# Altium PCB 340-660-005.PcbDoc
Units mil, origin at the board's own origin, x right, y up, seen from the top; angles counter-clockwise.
Board outline 988 x 985 mil, 2 copper layers (Top Layer, Bottom Layer), stack 61.756 mil thick; 90 components, 41 nets, 201 pads, 77 vias.
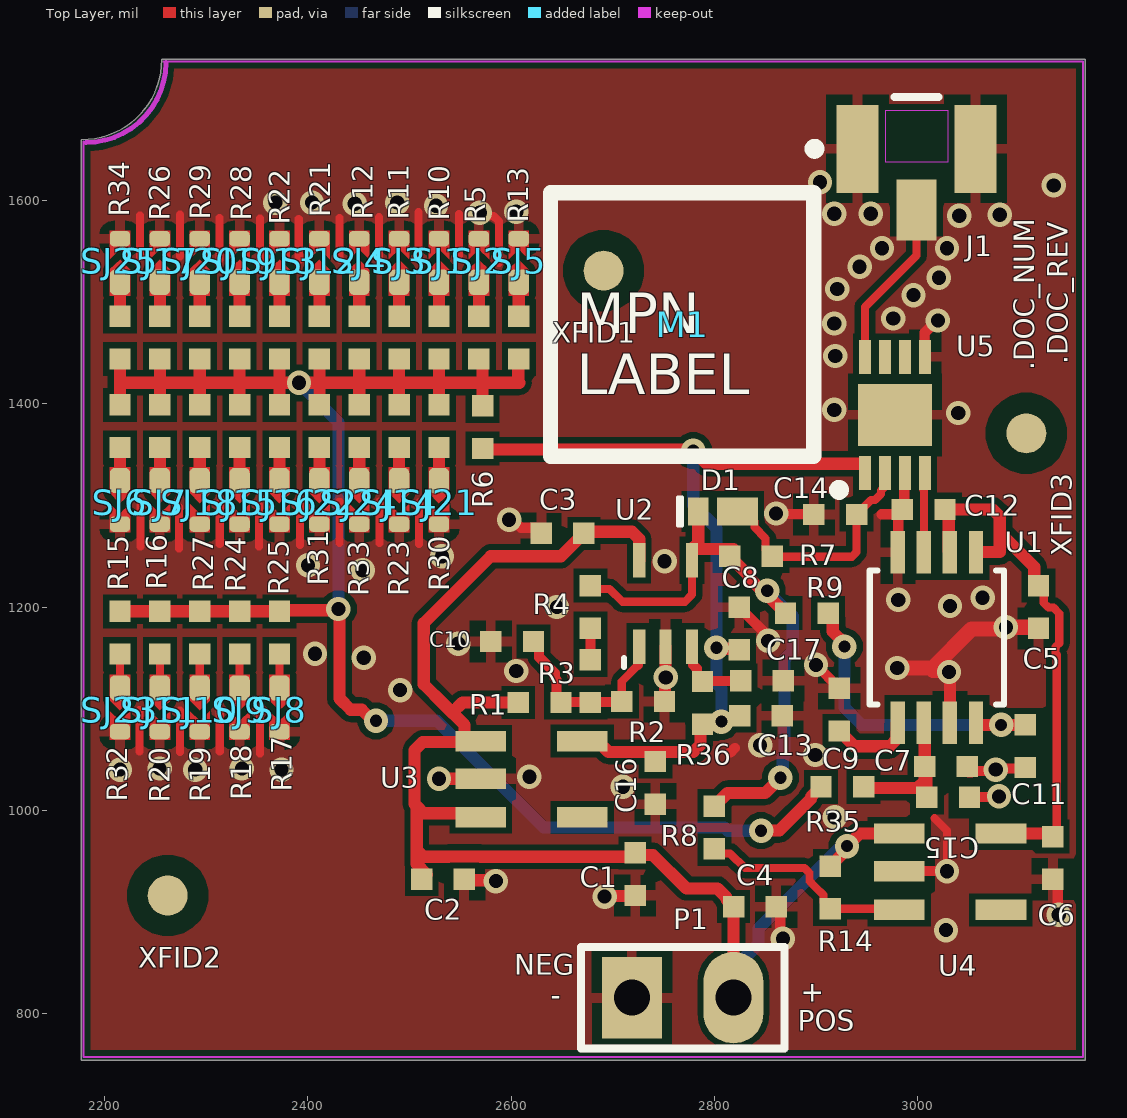
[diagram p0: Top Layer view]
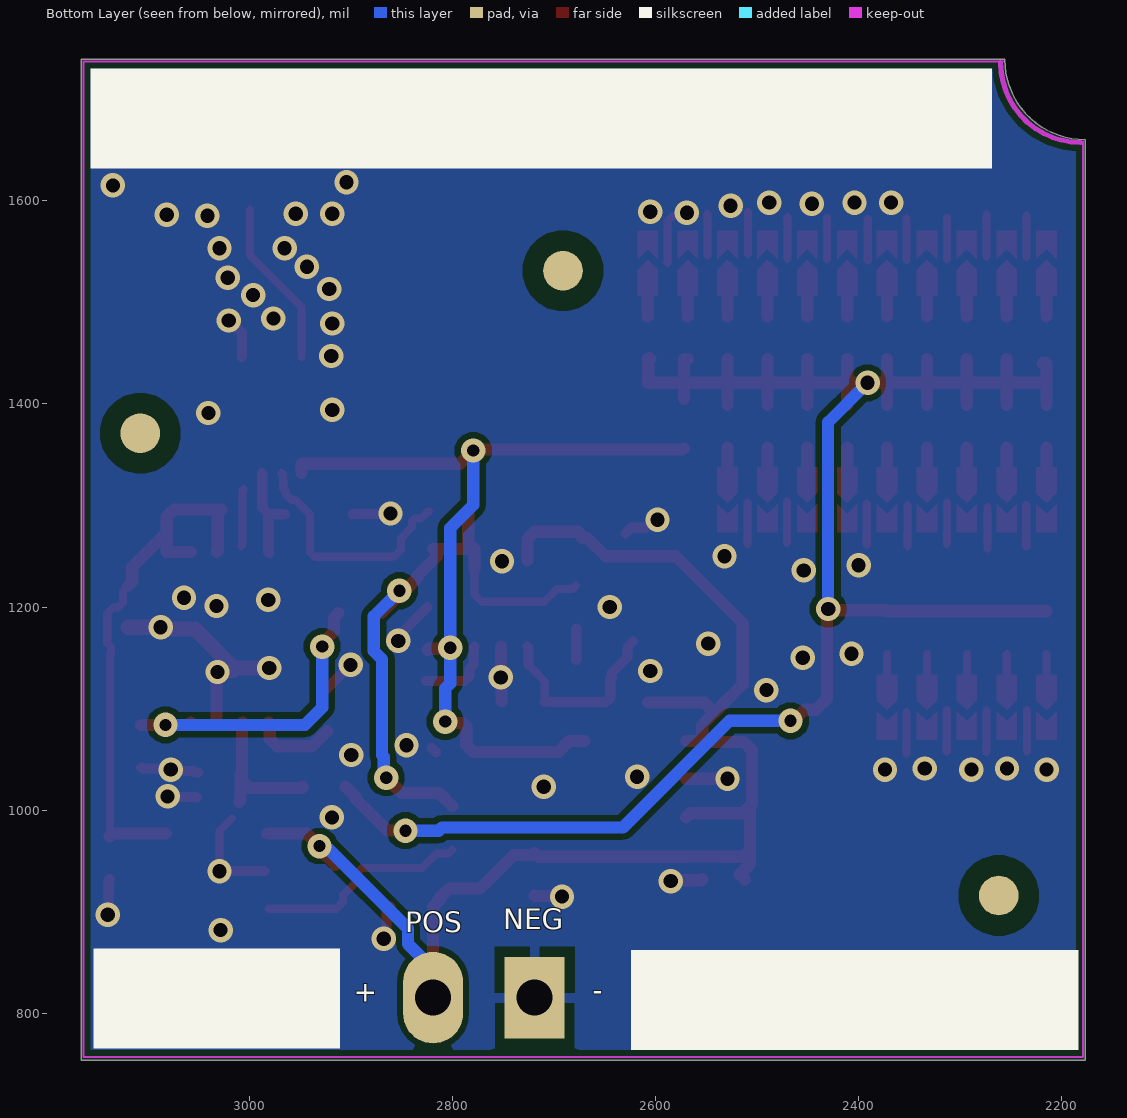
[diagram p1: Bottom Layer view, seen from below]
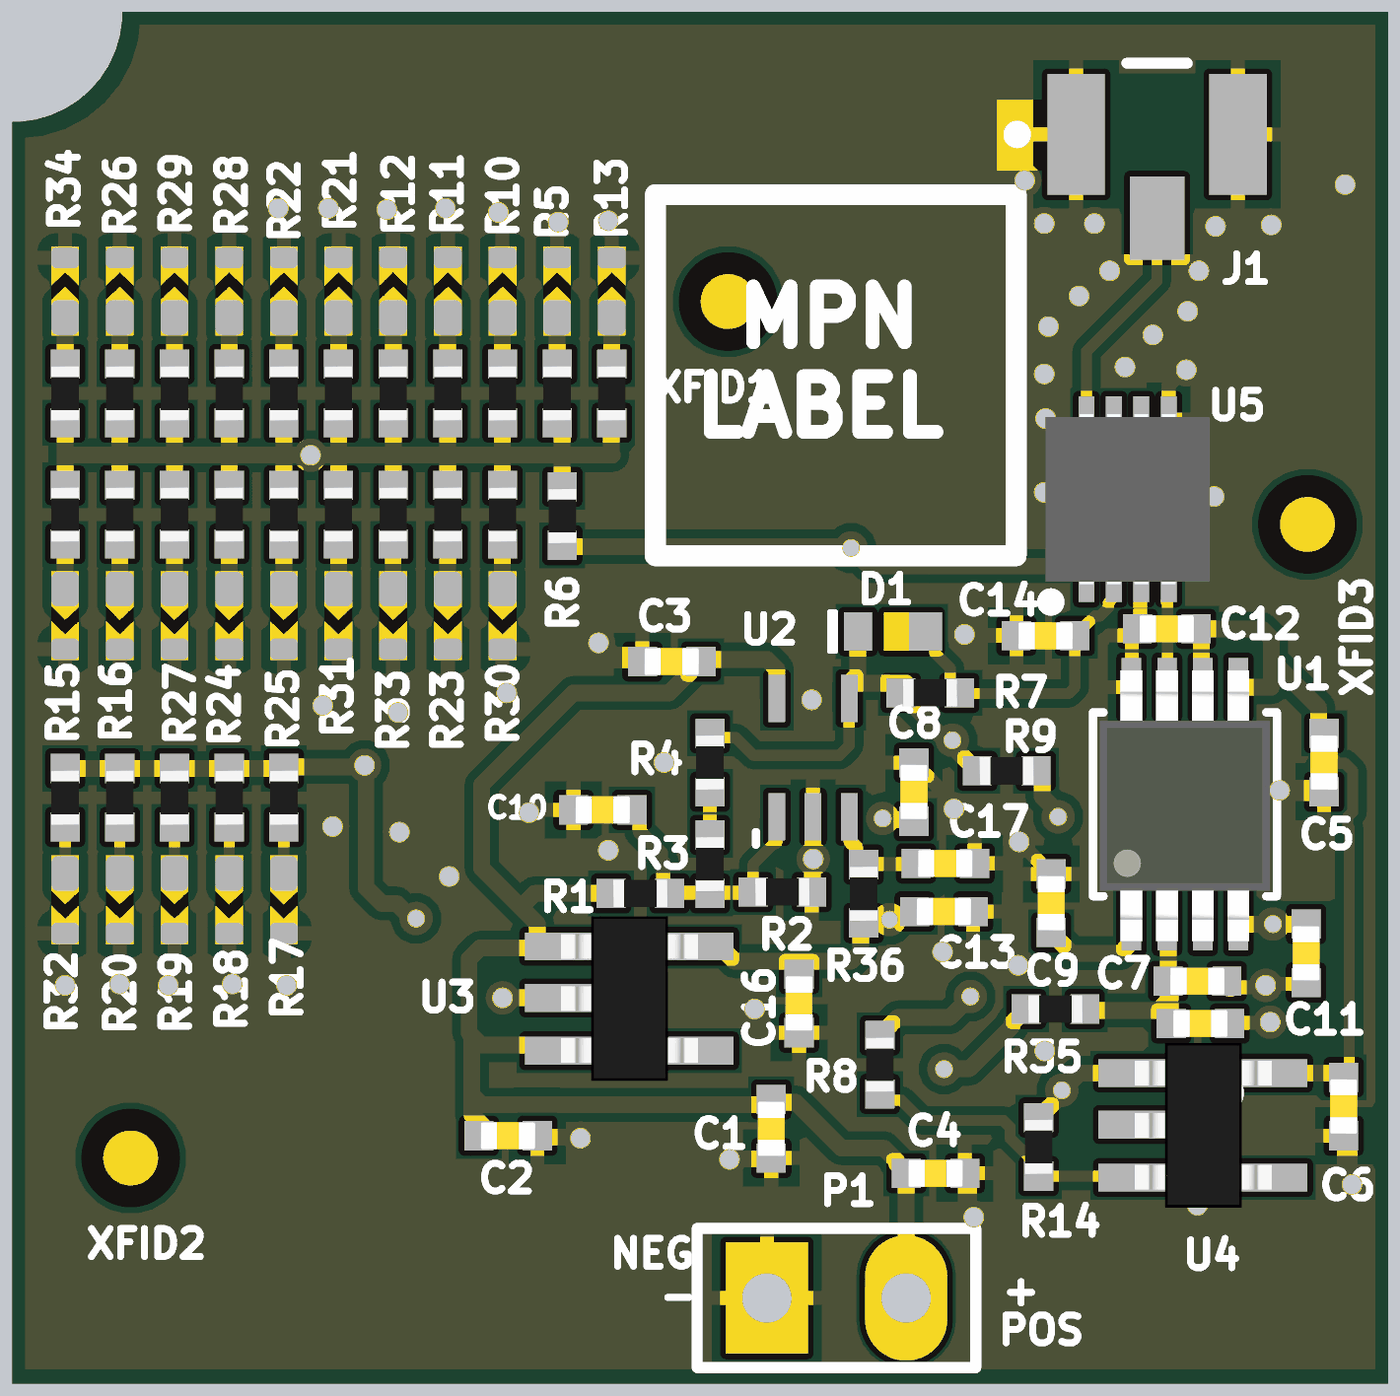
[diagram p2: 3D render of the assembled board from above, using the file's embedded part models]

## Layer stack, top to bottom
Top Solder: solder mask 1, SM-001, Dk 4
Top Layer: signal copper 1.378
Dielectric 1: core 59, Core-043, Dk 4.3
Bottom Layer: signal copper 1.378
Bottom Solder: solder mask 1, SM-001, Dk 4

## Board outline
2177,754 3165,754 3165,1739 2256.09,1739 2256.09,1738.7 cw(c2177.35,1738.7) 2177.35,1659.96 2177,1659.96

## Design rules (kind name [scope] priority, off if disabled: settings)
AssemblyTestPointUsage [All] p1 off:
AssemblyTestpoint [All] p1 off: testpointundercomponent=TRUE minsize=40 maxsize=100 preferedsize=60 minholesize=0 maxholesize=40 preferedholesize=32 testpointgrid=1 usegrid=TRUE gridtolerance=0.01 allowsidetop=TRUE allowsidebottom=TRUE
Clearance Clearance_MountingHole [HasFootprint('FID_TOP_BOT_39')] p1: gap=20 ignorepadtopadclearanceinfootprint=FALSE
Clearance Clearance_PadToPad [IsPad vs IsPad] p2: gap=8 ignorepadtopadclearanceinfootprint=FALSE except(0: Arc-Hole Track-Hole SMDPad-Hole THPad-Hole Via-Hole Fill-Hole Poly-Hole Region-Hole Text-Hole)
Clearance Clearance_Region [All] p3: gap=6 ignorepadtopadclearanceinfootprint=FALSE except(0: Arc-Hole Track-Hole SMDPad-Hole THPad-Hole Via-Hole Fill-Hole Poly-Hole Region-Hole Text-Hole)
Clearance Clearance_Track [(IsTrack)] p4: gap=8 ignorepadtopadclearanceinfootprint=FALSE except(0: Arc-Hole Track-Hole SMDPad-Hole THPad-Hole Via-Hole Fill-Hole Poly-Hole Region-Hole Text-Hole)
Clearance [All] p5: gap=12 ignorepadtopadclearanceinfootprint=FALSE except(0: Arc-Hole Track-Hole SMDPad-Hole THPad-Hole Via-Hole Fill-Hole Poly-Hole Region-Hole Text-Hole)
ComponentClearance "'Default' PADS rule_12" [All] p1 off: gap=10 collisioncheckmode=3 verticalgap=10 showdistances=FALSE
FabricationTestPointUsage [All] p1 off: valid=0 allowmultiple=FALSE
FabricationTestpoint [All] p1 off: side=3 testpointundercomponent=TRUE minsize=40 maxsize=100 preferedsize=60 minholesize=0 maxholesize=40 preferedholesize=32 testpointgrid=1 allowsidetop=TRUE allowsidebottom=TRUE usegrid=TRUE gridtolerance=0.01
FlightTimeFalling "'Default' PADS rule_6" [All] p1: maximum=10.00
FlightTimeRising "'Default' PADS rule_5" [All] p1: maximum=10.00
Length "'Default' PADS rule" [All] p1: maxlimit=50000 minlimit=0
MaxMinImpedance "'Default' PADS rule_4" [All] p1: minimum=50.00 maximum=150.0
ParallelSegment "'Default' PADS rule_3" [All] p1: limit=1000 gap=200
ParallelSegment "'Default' PADS rule_2" [All] p2: limit=1000 gap=200
PlaneConnect [All] p1: planeconnectstyle=Relief reliefexpansion=24 reliefentries=4 reliefconductorwidth=70 reliefairgap=10
PolygonConnect PolygonConnect_Luxeon [(HasFootprint('LED_K2_FR4_NOLEN'))] p1: connectstyle=Direct reliefconductorwidth=10 reliefentries=4 polygonreliefangle="90 Angle" airgapwidth=10
PolygonConnect PolygonConnect_Via [IsVia] p2: connectstyle=Direct reliefconductorwidth=10 reliefentries=4 polygonreliefangle="45 Angle" airgapwidth=10
PolygonConnect PolygonConnect_NotVIA [NOT IsVia] p3: connectstyle=Relief reliefconductorwidth=10 reliefentries=4 polygonreliefangle="90 Angle" airgapwidth=10
RoomDefinition 340-660-005 [InComponentClass('340-660-005')] p1: confinementstyle=ConfineIn formatcopy=TRUE lockcomponents=FALSE outline 3236,1781 2149,1781 2149,735 3236,735
RoutingVias [All] p1: holewidth=10 width=22 viastyle="Through Hole" minholewidth=6 minwidth=16 maxholewidth=28 maxwidth=50
SilkToSolderMaskClearance SilkscreenOverComponentPads [IsPad] p1: minsilkscreentomaskgap=10 clearancetoexposedcopper=TRUE
SolderMaskExpansion [All] p1: expansion=4 istentingtop=FALSE
Width [All] p1: maxlimit=80 minlimit=6 preferedwidth=15 minimp=50.000000 maximp=50.000000 favimp=50.000000
23 further rules are at their usual default settings.

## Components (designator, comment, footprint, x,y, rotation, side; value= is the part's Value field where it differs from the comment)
C1 "CL05A106MP5NUNC" 0402CAP 2722,937 r90 top value=10uF
C2 "GMK105BJ104KV-F" 0402CAP 2533,932 r180 top value=0.1uF
C3 "GMK105BJ104KV-F" 0402CAP 2650.5,1272.5 r0 top value=0.1uF
C4 "ECJ-0EC1H221J" 0402CAP 2840,905 r180 top value=220pF
C5 "ECJ-0EC1H221J" 0402CAP 3119,1200 r90 top value=220pF
C6 "GMK105BJ104KV-F" 0402CAP 3133,953 r90 top value=0.1uF
C7 "CL05A106MP5NUNC" 0402CAP 3028,1043 r180 top value=10uF
C8 "GMK105BJ104KV-F" 0402CAP 2824.42,1178.87 r270 top value=0.1uF
C9 "GMK105BJ104KV-F" 0402CAP 2923,1099 r270 top value=0.1uF
C10 "0402ZD105KAT2A" 0402CAP 2601,1166 r0 top value=1.0uF
C11 "ECJ-0EC1H221J" 0402CAP 3106,1063 r90 top value=220pF
C12 "ECJ-0EC1H221J" 0402CAP 3006,1296 r0 top value=220pF
C13 "GMK105BJ104KV-F" 0402CAP 2845.96,1092.98 r180 top value=0.1uF
C14 "ECJ-0EC1H221J" 0402CAP 2919,1291 r0 top value=220pF
C15 "ECJ-0EC1H221J" 0402CAP 3030.16,1012.58 r180 top value=220pF
C16 "CL05A106MP5NUNC" 0402CAP 2742,1027 r90 top value=10uF
C17 "0402ZD105KAT2A" 0402CAP 2846.96,1127.54 r180 top value=1.0uF
D1 "NSR20F40NXT5G" DIODE_2-DSN_ON 2809,1294 r0 top
J1 "" CONN_HRS-U.FL-R-SMT_V 2999,1651 r180 top
M1 "MPN Label" LABEL_7x7mm 2769,1478 r0 top
P1 "Header 2" HDR1X2 2718.83,815.47 r0 top
R1 "CRCW040210M0FKED" 0402RES 2628,1106 r180 top value=10.0MEG
R2 "CRCW040210M0FKED" 0402RES 2730,1107 r180 top value=10.0MEG
R3 "CRCW040210M0FKED" 0402RES 2678,1127 r270 top value=10.0MEG
R4 "CRCW040210M0FKED" 0402RES 2678,1200 r270 top value=10.0MEG
R5 "CRCW040210M0FKED" 0402RES 2568.25,1465.02 r270 top value=10.0MEG
R6 "4.02MEG" 0402RES 2572,1377 r270 top
R7 "RC0402FR-07100KL" 0402RES 2836,1250 r180 top value=100K
R8 "RCS04021K00FKED" 0402RES 2800,983 r90 top value=1.0K
R9 "CRCW040210K0FKEDHP" 0402RES 2891,1194 r180 top value=10.0K
R10 "CRCW040210M0FKED" 0402RES 2529,1465.02 r270 top value=10.0MEG
R11 "CRCW040210M0FKED" 0402RES 2489.75,1465.02 r270 top value=10.0MEG
R12 "CRCW040210M0FKED" 0402RES 2450.5,1465.02 r270 top value=10.0MEG
R13 "CRCW040210M0FKED" 0402RES 2607.5,1465.02 r270 top value=10.0MEG
R14 "RCS04021K00FKED" 0402RES 2914,924 r270 top value=1.0K
R15 "CRCW040210M0FKED" 0402RES 2215,1378 r90 top value=10.0MEG
R16 "CRCW040210M0FKED" 0402RES 2254.25,1378 r90 top value=10.0MEG
R17 "CRCW040210M0FKED" 0402RES 2372,1174.73 r90 top value=10.0MEG
R18 "CRCW040210M0FKED" 0402RES 2332.75,1174.73 r90 top value=10.0MEG
R19 "CRCW040210M0FKED" 0402RES 2293.5,1174.73 r90 top value=10.0MEG
R20 "CRCW040210M0FKED" 0402RES 2254.25,1174.73 r90 top value=10.0MEG
R21 "CRCW040210M0FKED" 0402RES 2411.25,1465.02 r270 top value=10.0MEG
R22 "CRCW040210M0FKED" 0402RES 2372,1465.02 r270 top value=10.0MEG
R23 "CRCW040210M0FKED" 0402RES 2489.75,1378 r90 top value=10.0MEG
R24 "CRCW040210M0FKED" 0402RES 2332.75,1378 r90 top value=10.0MEG
R25 "CRCW040210M0FKED" 0402RES 2372,1378 r90 top value=10.0MEG
R26 "CRCW040210M0FKED" 0402RES 2254.25,1465.02 r270 top value=10.0MEG
R27 "CRCW040210M0FKED" 0402RES 2293.5,1378 r90 top value=10.0MEG
R28 "CRCW040210M0FKED" 0402RES 2332.75,1465.02 r270 top value=10.0MEG
R29 "CRCW040210M0FKED" 0402RES 2293.5,1465.02 r270 top value=10.0MEG
R30 "CRCW040210M0FKED" 0402RES 2529,1378 r90 top value=10.0MEG
R31 "CRCW040210M0FKED" 0402RES 2411.25,1378 r90 top value=10.0MEG
R32 "CRCW040210M0FKED" 0402RES 2215,1174.73 r90 top value=10.0MEG
R33 "CRCW040210M0FKED" 0402RES 2450.5,1378 r90 top value=10.0MEG
R34 "CRCW040210M0FKED" 0402RES 2215,1465.02 r270 top value=10.0MEG
R35 "RCS04021K00FKED" 0402RES 2926,1023 r180 top value=1.0K
R36 "CRCW040210M0FKED" 0402RES 2788.33,1105.72 r270 top value=10.0MEG
SJ1 "ISENSEA" SOLDERJUMPER_ARROW_NOPASTE 2529,1541 r90 top
SJ2 "ISENSEA" SOLDERJUMPER_ARROW_NOPASTE 2568.25,1541 r90 top
SJ3 "ISENSEA" SOLDERJUMPER_ARROW_NOPASTE 2489.75,1541 r90 top
SJ4 "ISENSEA" SOLDERJUMPER_ARROW_NOPASTE 2450.5,1541 r90 top
SJ5 "ISENSEA" SOLDERJUMPER_ARROW_NOPASTE 2607.5,1541 r90 top
SJ6 "ISENSEA" SOLDERJUMPER_ARROW_NOPASTE 2215,1303 r270 top
SJ7 "ISENSEA" SOLDERJUMPER_ARROW_NOPASTE 2254.25,1303 r270 top
SJ8 "ISENSEA" SOLDERJUMPER_ARROW_NOPASTE 2372,1098.82 r270 top
SJ9 "ISENSEA" SOLDERJUMPER_ARROW_NOPASTE 2332.75,1098.82 r270 top
SJ10 "ISENSEA" SOLDERJUMPER_ARROW_NOPASTE 2293.5,1098.82 r270 top
SJ11 "ISENSEA" SOLDERJUMPER_ARROW_NOPASTE 2254.25,1098.82 r270 top
SJ12 "ISENSEA" SOLDERJUMPER_ARROW_NOPASTE 2411.25,1541 r90 top
SJ13 "ISENSEA" SOLDERJUMPER_ARROW_NOPASTE 2372,1541 r90 top
SJ14 "ISENSEA" SOLDERJUMPER_ARROW_NOPASTE 2489.75,1303 r270 top
SJ15 "ISENSEA" SOLDERJUMPER_ARROW_NOPASTE 2332.75,1303 r270 top
SJ16 "ISENSEA" SOLDERJUMPER_ARROW_NOPASTE 2372,1303 r270 top
SJ17 "ISENSEA" SOLDERJUMPER_ARROW_NOPASTE 2254.25,1541 r90 top
SJ18 "ISENSEA" SOLDERJUMPER_ARROW_NOPASTE 2293.5,1303 r270 top
SJ19 "ISENSEA" SOLDERJUMPER_ARROW_NOPASTE 2332.75,1541 r90 top
SJ20 "ISENSEA" SOLDERJUMPER_ARROW_NOPASTE 2293.5,1541 r90 top
SJ21 "ISENSEA" SOLDERJUMPER_ARROW_NOPASTE 2529,1303 r270 top
SJ22 "ISENSEA" SOLDERJUMPER_ARROW_NOPASTE 2411.25,1303 r270 top
SJ23 "ISENSEA" SOLDERJUMPER_ARROW_NOPASTE 2215,1098.82 r270 top
SJ24 "ISENSEA" SOLDERJUMPER_ARROW_NOPASTE 2450.5,1303 r270 top
SJ25 "ISENSEA" SOLDERJUMPER_ARROW_NOPASTE 2215,1541 r90 top
U1 "MAX2752EUA+" 21-0036K_MXM 3019,1170 r90 top
U2 "TLV3691IDCKT" SC70/5 2726,1156 r90 top
U3 "S-1318D18-M5T1U4" SOT-23/5 2614,1028 r90 top
U4 "TPS7A0228PDBVR" SOT-23/5 3026,937 r90 top value=2.8V
U5 "ADG901BCPZ-500RL7" SON50P300X300X85-9N-D 2977.84,1389.09 r90 top
XFID1 "" FID_TOP_BOT_39 2691.1,1531.1 r0 top
XFID2 "" FID_TOP_BOT_39 2262.1,916.1 r0 top
XFID3 "" FID_TOP_BOT_39 3107.1,1371.1 r0 top

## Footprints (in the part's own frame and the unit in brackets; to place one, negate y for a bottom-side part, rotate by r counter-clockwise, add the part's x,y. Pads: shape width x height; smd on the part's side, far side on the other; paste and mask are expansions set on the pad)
21-0036K_MXM [mil]
  rect 42x14 smd: 1(-84,38.4) 2(-84,12.8) 3(-84,-12.8) 4(-84,-38.4) 5(84,-38.4) 6(84,-12.8) 7(84,12.8) 8(84,38.4)
  silkscreen extent -66,-66 66,66, body extent -98,-61 96,61, height 43
0402CAP [mil]
  rect 21x21 smd: 1(-21,0) 2(21,0)
  body extent -20,-10 20,10, height 20
0402RES [mil]
  rect 21x21 smd: 1(-21,0) 2(21,0)
  body extent -20,-10 20,10, height 12
CONN_HRS-U.FL-R-SMT_V [mm] "SMD, 3-Leads, Body 2.6x2.6mm"
  rect 1.05x2.2 smd: 1(1.475,0) 2(-1.475,0)
  rect 1x1.524 smd: 3(0,1.525)
  silkscreen extent -0.55,-1.3 2.67,0.12, body extent -1.3,-1.3 1.3,1.3, height 1.25
DIODE_2-DSN_ON [mm] "Molded Diode, 2-Leads, Body 1.60x0.80mm, IPC High Density"
  rect 1.016x0.7 smd paste-0.381: A(0.349,0)
  rect 0.52x0.7 smd: C(-0.629,0)
  silkscreen extent -1.14,-0.36 -1.04,0.36, body extent -0.8,-0.4 0.8,0.4, height 0.31
FID_TOP_BOT_39 [mil] "Fiducial mark, both sides of the board, 39mil (1mm) copper, 45mil soldermask"
  round 39.37 smd paste-19.68 mask+15.75: 0(-0.1,-0.1)
  round 39 smd far side paste-19.68 mask+15.75: 1(-0.1,-0.1)
HDR1X2 [mm] "Connector; Header; 2 Position"
  rect 1.5x2.032 hole 0.9: 1(0,0)
  oval 1.5x2.286 hole 0.9: 2(2.54,0)
  silkscreen extent -1.27,-1.27 3.81,1.27
LABEL_7x7mm [mil] "Box for MPN Lable, 7x7mm"
  silkscreen extent -130,-130 129,130
SC70/5 [mil]
  rect 34x12 smd: 1(5,0) 2(5,-26) 3(5,-52) 4(90,-52) 5(90,0)
  silkscreen extent -15,15 -6,15, body extent 10,-68 89,11, height 30
SOLDERJUMPER_ARROW_NOPASTE [mil] "SOLDERJUMPER_ARROW_NOPASTE"
  rrect50% 25x20 smd paste+0 mask+0: 1(-21.5,0)
  rrect50% 15x20 smd paste+0 mask+0: 2(21.5,0)
  Top Layer region: 1.37,10 11,0 1.37,-10 29.47,-10 29.47,10
  Top Layer region: -34.44,10 -8.69,10 0.68,-0.1 -9.22,-10 -34.44,-10
SON50P300X300X85-9N-D [mm]
  rect 0.85x0.292 smd: 1(-1.45,0.75) 2(-1.45,0.25) 3(-1.45,-0.25) 4(-1.45,-0.75) 5(1.45,-0.75) 6(1.45,-0.25) 7(1.45,0.25) 8(1.45,0.75)
  rect 1.55x1.84 smd: 9(0,0)
  silkscreen extent -2,1.27 -1.75,1.52, body extent -1.55,-1.5 1.55,1.5, height 0.85
SOT-23/5 [mil]
  rect 20x50 smd: 1(40,44) 2(3,44) 3(-35,44) 4(-35,-56) 5(40,-56)
  body extent -57,-56 62,43, height 43

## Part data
C1 C7 C16: library part CAP_0402_10uF_X5R_10V, "CAP CER 10UF 10V X5R 0402", Supplier Part Number 1=82AC9190, Voltage=10V
C2 C3 C6 C8 C9 C13: library part CAP_0402_0.1uF_X5R_35V, "CAP CER .10UF 35V X5R 0402", Supplier Part Number 1=587-1994-1-ND, Voltage=35V
C4 C5 C11 C12 C14 C15: library part CAP_0402_220pF_NP0_50V, "CAP 220PF 50V CERAMIC 0402 SMD", Supplier Part Number 1=PCC221CQCT-ND, Voltage=50V
C10 C17: library part CAP_0402_1uF_X5R_10V, "CAP CERAMIC 1UF 10V X5R 0402", Supplier Part Number 1="Digi-Key - 490-5409-1-ND", Voltage=10V
D1: library part Diode_SHOTTKY_NSR20F40NXT5G, "Diode Schottky 40V 2A (DC) Surface Mount 2-DSN (1.6x.80)", Current=2A, Supplier Part Number 1=NSR20F40NXT5GOSCT-ND, Voltage=40V
J1: library part CONN_Hirose_U.FL-R-SMT(10), "Ultra Small Surface Mount Coaxial Connector, 50 Ohm, -40 to 90 degC, 3-Pin SMD, RoHS, Tape and Reel", Colour=Black, Current Rating="3 A", Max Operating Temperature=105degC, Min Operating Temperature=-65degC, Package Quantity=50, Supplier Part Number 1=H122041-ND
M1: library part Label_MPN, "Serial Number Label Placeholder"
P1: "Header, 2-Pin"
R1 R2 R3 R4 R5 R10 R11 R12 R13 R15 R16 R17 R18 R19 R20 R21 R22 R23 R24 R25 R26 R27 R28 R29 R30 R31 R32 R33 R34 R36: library part Res_0402_10MEG_1%, "RES 10M OHM 1/16W 1% 0402 SMD", Supplier Part Number 1=541-10.0MLDKR-ND
R6: library part Res_0402_4.02MEG_1%, "RES 4.02M OHM 1/16W 1% 0402 SMD", Supplier Part Number 1=541-4.02MLCT-ND
R7: library part Res_0402_100K_1%, "RES 100K OHM 1/16W 1% 0402 SMD", Supplier Part Number 1=311-100KLRCT-ND
R8 R14 R35: library part Res_0402_1.0K_1%, "RES SMD 1K OHM 1% 1/5W 0402", Supplier Part Number 1=541-2888-1-ND
R9: library part Res_0402_10.0K_1%, "RES 10K OHM 1/10W 1% 0402 SMD", Supplier Part Number 1=CRCW040210K0FKEDHP/BKN
SJ1 SJ2 SJ3 SJ4 SJ5 SJ6 SJ7 SJ8 SJ9 SJ10 SJ11 SJ12 SJ13 SJ14 SJ15 SJ16 SJ17 SJ18 SJ19 SJ20 SJ21 SJ22 SJ23 SJ24 SJ25: library part SOLDERJUMPER_OPEN, "SMD Solder JUMPER   Solder the two pads together to create a connection, or remove the solder to break it.REFLOW - Use this footprint for solder paste and reflow ovens. WAVE - Use this footprint for hand-soldering (larger pads).    CLOSED - Has a trace between the two pads to ensure it is closed by default.  The trace needs to be cut to disable the jumper, and can be closed again by creating a solder bridge between the two pads."
U1: "RF IC VCO ISM 2.025GHz ~ 2.165GHz On-Chip Tank Circuit 8-uMAX/uSOP"
U2: "IC COMPARATOR NANO-POWER SC70-5", Supplier Part Number 1=595-TLV3691IDCKT
U3: "Ultra-Low Quescent Current Linear Voltage Regulator IC Positive Fixed 1.8V 100mA SOT-23-5", Supplier Part Number 1=1662-S-1318D18-M5T1U4CT-ND
U4: "2.8V, 1-µA, ultra-low-IQ, 200-mA low-dropout (LDO) regulator in a small-sized", Supplier Part Number 1=296-TPS7A0228PDBVRCT-ND
U5: library part ADG901BCPZ, "RF Switch IC General Purpose SPST 2.5 GHz 50Ohm 8-LFCSP (3x3)", Supplier Part Number 1=505-ADG901BCPZ-500RL7CT-ND
XFID1 XFID2 XFID3: library part MOUNT_FIDUCIAL, "Mounting Hole"

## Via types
v1: diameter 24, hole 14, Top Layer to Bottom Layer, tented both sides, 67 vias
v2: diameter 24, hole 12, Top Layer to Bottom Layer, tented both sides, 10 vias

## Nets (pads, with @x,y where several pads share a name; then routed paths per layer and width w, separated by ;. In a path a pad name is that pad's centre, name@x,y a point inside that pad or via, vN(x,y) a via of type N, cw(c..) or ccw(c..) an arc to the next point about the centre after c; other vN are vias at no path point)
GND: C1.1 C2.1 C3.1 C4.1 C5.1 C6.1 C7.1 C8.1 C9.1 C10.1 C11.1 C12.1 C13.1 C14.1 C15.1 C16.1 C17.1 J1.1 J1.2 P1.1 R2.1 SJ1.2 SJ2.2 SJ3.2 SJ4.2 SJ5.2 SJ6.2 SJ7.2 SJ8.2 SJ9.2 SJ10.2 SJ11.2 SJ12.2 SJ13.2 SJ14.2 SJ15.2 SJ16.2 SJ17.2 SJ18.2 SJ19.2 SJ20.2 SJ21.2 SJ22.2 SJ23.2 SJ24.2 SJ25.2 U1.3 U1.8 U2.2 U3.2 U4.2 U5.3 U5.5 U5.9 | length 1860.9
  Top Layer w8: 2234.13,1057.61 2234.13,1098.43 ; 2234.67,1544.5 2234.67,1585.33 ; 2235.04,1259.51 2235.04,1300.34 ; 2273.26,1257.62 2273.26,1298.45 ; 2274.01,1545.26 2274.01,1586.08 ; 2274.15,1057.37 2274.15,1098.2 ; 2313,1541.89 2313,1582.72 ; 2313.16,1261.95 2313.16,1302.78 ; 2313.23,1057.96 2313.23,1098.79 ; 2351.94,1259.51 2351.94,1300.34 ; 2352.69,1541.49 2352.69,1582.32 ; 2352.78,1055.71 2352.78,1096.54 ; 2391,1540.89 2391,1581.72 ; 2392.04,1261.01 2392.04,1301.84 ; 2431,1263.08 2431,1303.91 ; 2431,1541.89 2431,1582.72 ; 2469.97,1542.81 2469.97,1583.64 ; 2470.34,1263.08 2470.34,1303.91 ; 2508.94,1547.7 2508.94,1588.53 ; 2509.31,1262.04 2509.31,1302.86 ; 2548.84,1546.01 2548.84,1586.84 ; v1(2569,1588) 2572.06,1584.94 2582.74,1584.94 2588,1579.68 2588,1538.86 ; 3016.72,992.08 3029,979.81 v1(3029,940)
  Top Layer w10: v1(2598,1285.91) 2601.79,1285.91 2609.69,1278 2624,1278 C3.1 ; 2816,1057 2820.32,1061.32 ; C8.1 2850.46,1173.83 2850.46,1169.34 v1(2853.14,1166.66) ; v1@2842.32,1061.32 v1(2845,1064) ; v1(2860.75,1292) 2861.25,1291.5 2897.5,1291.5 C14.1 ; C4.1 2864.79,901.21 2864.79,876.21 v1(2867.47,873.53) ; v1(2900,1143) C9.1 ; 2964.5,1291.26 2980.26,1291.26 C12.1@2981,1292 ; U1.8@2980,1253 U1.8@2980.6,1253.6 ; U1.8 U1.8@2980.6,1253.6 ; U4.2@2985,940 v1(3029,940) ; U5.3 2986.93,1331.25 2986.93,1297.93 C12.1 C12.1@2981,1292 ; U5.5 3007,1446.54 3007,1470 3019,1482 v1(3020,1482) ; C7.1@3050,1037 3053,1037 3055,1039 3055.5,1038.5 3075.5,1038.5 v1(3077,1040) 3078,1041 3105,1041 C11.1 ; C15.1 3052.16,1012.58 3053.16,1013.58 3053.66,1013.08 3079.66,1013.08 v1(3080.16,1013.58) ; C6.1@3137,932 3138,931 3138,898 v1(3139,897) ; U1.8@2980.6,1253.6 2981,1254 C12.1@2981,1292
  Top Layer w12: v1(2529,1031) U3.2 ; C2.1 2554.9,931.1 2584.1,931.1 v1(2585,930.2) ; v1(2692,915) 2697,915 2697.5,915.5 2718.5,915.5 C1.1@2719,916 ; R2.1 2751.57,1107.57 2751.57,1130.14 v1(2752.14,1130.71) 2752,1130.85 U2.2 ; 3015,1136 v1(3031,1136) 3031.9,1136 3031.9,1086.1 U1.3
  Top Layer w15: v1(2980,1140) 3015,1140 3053.28,1178.28 3085.28,1178.28 v1(3087,1180) C5.1@3119,1180
  other v1: 3028,882 2918.4,992.89 2710,1023 2618,1033 2215,1040 2289,1040 2374,1040 2254,1041 2335,1041 2899.3,1054.38 2490.72,1118.18 2605,1137 2455,1150 2407,1154 2548,1164 2645,1200 3032,1201 2981,1207 3064,1209 2454,1236 2400,1241 2751,1245 2532,1250 3040,1391 2918,1394 2919,1447 2918,1479 2976,1484 2996,1507 2921,1513 3021,1524 2943,1535 2965,1553 3029,1553 3041,1585 3081,1586 2918,1587 2954,1587 2605,1589 2526,1595 2446,1597 2368,1598 2404,1598 2488,1598 3134,1615 2904,1618
NetC5_2: C5.2 C6.2 C12.2 U1.5 U1.6 U4.5 | length 539.5
  Top Layer w8: C5.2 3124.16,1215.84 3124.16,1204.19 3128.84,1199.5 3133.64,1199.5 3139.5,1193.64 3139.5,1164.36 3135.88,1160.74 3135.88,1154.12 3137,1153 C6.2@3137,978.5
  Top Layer w12: U1.6 3030.8,1255 3030.8,1292.2 C12.2 3073.94,1296 3080.97,1288.97 3080.97,1273.36 ; U1.5 3080.97,1254 3080.97,1273.36 ; U4.5 3134,977 C6.2@3137,974 ; C5.2 3114.94,1225.06 3114.94,1239.39 3080.97,1273.36
NetC7_2: C7.2 C15.2 R35.1 U1.2 | length 150.9
  Top Layer w12: R35.1 2948,1022 2999.97,1022 3007,1029.03 C7.2@3007,1037 ; U1.2 3007,1085.2 C7.2@3007,1037 ; C15.2@3010,1008 3008.5,1009.5 3008.5,1029.03 3008.5,1035.5 C7.2@3007,1037
NetC9_2: C9.2 U1.1 | length 82.1
  Top Layer w12: C9.2 2938,1063 2972.57,1063 2979.6,1070.03 2979.6,1085 U1.1
NetC10_2: C10.2 R1.1 R2.2 R3.2 U2.1 | length 188.9
  Top Layer w8: R2.2@2708.88,1107.12 2708.88,1126.64 2725,1142.76
  Top Layer w10: C10.2 2627.5,1160.5 2627.5,1150.44 2642.94,1135 2642.94,1130.1 2644.48,1128.56 2644.48,1110.52 R1.1 2649.5,1106.5 R3.2@2678,1106.5 ; R3.2 2678.5,1106 2679,1106.5 R2.2@2705.15,1106.5 ; R2.2@2708.88,1107.12 R2.2 ; 2725,1142.76 2725,1160 U2.1
NetC11_2: C11.2 R9.1 U1.4 | length 310.9
  Top Layer w12: R9.1 2916.5,1189.5 2916.5,1175.75 2928,1164.25 v2(2928,1161) ; U1.4 3057.4,1085 3058.4,1084 v2(3082.2,1084) C11.2
  Bottom Layer w12: v2(2928,1161) 2928,1101 2945,1084 v2(3082.2,1084)
NetC14_2: C14.2 D1.A R7.1 U5.2 | length 235.4
  Top Layer w8: D1.A 2824,1294 2831,1287 2836.64,1287 2839.42,1284.22 2839.42,1278.58 2850.5,1267.5 2850.5,1256.5 R7.1 ; R7.1@2860.5,1249.5 2935.31,1249.5 2940,1254.19 C14.2 2954.27,1305.27 2958.21,1305.27 2964.06,1311.13 2964.06,1314.58 2966.25,1316.77 2966.25,1330.25 U5.2
NetC17_2: C17.2 R36.1 U2.3 | length 76.5
  Top Layer w10: U2.3 2779,1160 2779,1143 2782.83,1139.17 2782.83,1132.22 R36.1 2788.74,1127.13 2825.55,1127.13 C17.2
NetD1_C: D1.C R4.1 R7.2 R8.2 R9.2 U2.4 | length 593.2
  Top Layer w8: R4.1 2681.25,1217.75 2696.8,1217.75 2709.42,1205.13 2770.97,1205.13 2778,1212.16 U2.4@2778,1233.51
  Top Layer w12: U2.4@2778,1236.62 U2.4 ; D1.C 2784.25,1263.25 U2.4@2778,1257 ; R8.2 2813,1017 2850,1017 v2(2865,1032) ; R7.2 2833.87,1231.13 2833.87,1229.03 2844.61,1218.3 2849.72,1218.3 v2(2852.02,1216.01) ; R7.2@2818.85,1257 U2.4@2778,1257 ; v2@2854.31,1209.69 R9.2 ; U2.4 U2.4@2778,1257 ; U2.4 U2.4@2778,1257
  Bottom Layer w12: v2(2852.02,1216.01) 2877.14,1190.88 2877.14,1156.72 2869,1148.58 2869,1054.06 2867.3,1052.35 2867.3,1034.3 v2(2865,1032)
NetJ1_3: J1.3 U5.8 | length 165.8
  Top Layer w8: U5.8 2948.31,1495.31 2999,1546 J1.3
NetR3_1: R3.1 R4.2 | length 31
  Top Layer w10: R3.1 R4.2
NetR5_1: R5.1 SJ2.1 | length 33.5
  Top Layer w12: R5.1 SJ2.1
NetR8_1: R8.1 R14.2 U4.3 | length 213.7
  Top Layer w8: R8.1@2800,961 2803.5,957.5 2815.5,957.5 2830,943 2888.81,943 2893.5,938.31 2893.5,930.36 2899.36,924.5 2907.5,916.36 2907.5,909.5 R14.2 U4.3@2981,903
NetR10_1: R10.1 SJ1.1 | length 33.5
  Top Layer w12: R10.1 SJ1.1
NetR11_1: R11.1 SJ3.1 | length 33.7
  Top Layer w12: R11.1 2489.75,1488.75 2490,1489 2489.75,1489.25 SJ3.1
NetR12_1: R12.1 SJ4.1 | length 33.5
  Top Layer w12: R12.1 SJ4.1
NetR13_1: R13.1 SJ5.1 | length 33.5
  Top Layer w12: R13.1 SJ5.1
NetR15_1: R15.1 SJ6.1 | length 32.5
  Top Layer w12: SJ6.1 R15.1
NetR16_1: R16.1 SJ7.1 | length 32.5
  Top Layer w12: SJ7.1@2254.25,1324.5 R16.1
NetR17_1: R17.1 SJ8.1 | length 33.4
  Top Layer w8: SJ8.1 R17.1
NetR18_1: R18.1 SJ9.1 | length 33.4
  Top Layer w8: SJ9.1 R18.1
NetR19_1: R19.1 SJ10.1 | length 33.4
  Top Layer w8: SJ10.1 R19.1
NetR20_1: R20.1 SJ11.1 | length 33.4
  Top Layer w8: SJ11.1 R20.1
NetR21_1: R21.1 SJ12.1 | length 33.5
  Top Layer w12: R21.1 SJ12.1
NetR22_1: R22.1 SJ13.1 | length 33.5
  Top Layer w12: R22.1 SJ13.1
NetR23_1: R23.1 SJ14.1 | length 32.5
  Top Layer w12: SJ14.1 R23.1
NetR24_1: R24.1 SJ15.1 | length 32.5
  Top Layer w12: SJ15.1 R24.1
NetR25_1: R25.1 SJ16.1 | length 32.5
  Top Layer w12: SJ16.1 R25.1
NetR26_1: R26.1 SJ17.1 | length 33.5
  Top Layer w12: R26.1 SJ17.1
NetR27_1: R27.1 SJ18.1 | length 32.5
  Top Layer w12: SJ18.1 R27.1
NetR28_1: R28.1 SJ19.1 | length 33.5
  Top Layer w12: R28.1 SJ19.1
NetR29_1: R29.1 SJ20.1 | length 33.5
  Top Layer w12: R29.1 SJ20.1
NetR30_1: R30.1 SJ21.1 | length 32.5
  Top Layer w12: SJ21.1 R30.1
NetR31_1: R31.1 SJ22.1 | length 32.5
  Top Layer w12: SJ22.1@2411.25,1324.5 R31.1
NetR32_1: R32.1 SJ23.1 | length 33.4
  Top Layer w8: SJ23.1 R32.1
NetR33_1: R33.1 SJ24.1 | length 32.5
  Top Layer w12: SJ24.1 R33.1
NetR34_1: R34.1 SJ25.1 | length 33.5
  Top Layer w12: R34.1 SJ25.1
NetU1_7: U1.7 U5.4 | length 56.7
  Top Layer w8: U5.4@3005.53,1315.91 3006.46,1314.98 3006.46,1260.94 U1.7@3007.4,1260
VFREQ: R5.2 R6.1 R10.2 R11.2 R12.2 R13.2 R15.2 R16.2 R17.2 R18.2 R19.2 R20.2 R21.2 R22.2 R23.2 R24.2 R25.2 R26.2 R27.2 R28.2 R29.2 R30.2 R31.2 R32.2 R33.2 R34.2 R35.2 | length 1956.5
  Top Layer w12: R32.2 R20.2 R19.2 R18.2 R17.2 2373.13,1196.87 2428.87,1196.87 v1(2430,1198) 2431,1197 2431,1110 2442.22,1098.78 2452.97,1098.78 2463.75,1088 v2(2467,1088) ; R15.2 2215,1439.52 2215.47,1439.99 R34.2@2219.03,1439.99 ; 2219.03,1420.75 2254.25,1420.75 ; R16.2 2254.25,1420.75 ; R26.2 2254.25,1420.75 ; R27.2 2293.5,1420.75 ; R29.2 2293.5,1420.75 ; R24.2 2332.75,1420.75 ; R28.2 2332.75,1420.75 ; R25.2 2372,1420.75 ; R22.2 2372,1420.75 ; R31.2 2411.25,1420.75 ; R21.2 2411.25,1420.75 ; R33.2 2450.5,1420.75 ; R12.2 2450.5,1420.75 ; R23.2 2489.75,1420.75 ; R11.2 2489.75,1420.75 ; R30.2 2529,1420.75 ; R10.2 2529,1420.75 ; R6.1@2571.83,1405 2571.83,1420.75 ; R5.2@2571.83,1443.94 2571.76,1444.02 R5.2 2571.83,1440.44 2571.83,1420.75 ; R13.2@2604.97,1443.97 R13.2@2606,1445 ; R13.2 2607,1443.52 2607,1421.66 2607.92,1420.75 2571.83,1420.75 ; v2(2846.04,979.85) 2846.34,980.16 2864.16,980.16 2895,1011 2895,1013 R35.2 ; 2254.25,1420.75 2293.5,1420.75 ; 2293.5,1420.75 2332.75,1420.75 ; 2332.75,1420.75 2372,1420.75 ; 2372,1420.75 2411.25,1420.75 ; 2411.25,1420.75 2450.5,1420.75 ; 2450.5,1420.75 2489.75,1420.75 ; 2489.75,1420.75 2529,1420.75 ; 2529,1420.75 2571.83,1420.75
  Bottom Layer w12: v1(2391.19,1420.66) 2430,1381.85 v1(2430,1198) v1@2426.75,1198 ; v2(2467,1088) 2527,1088 2632,983 2810.04,983 2813.19,979.85 v2(2846.04,979.85)
VREF: C8.2 C13.2 C16.2 R6.2 R36.2 U3.5 U5.1 | length 854.3
  Top Layer w12: R6.2 2573,1355 2778.33,1355 2792.33,1341 2948.06,1341 2948.31,1340.75 U5.1 ; U3.5 2685,1068 2695.69,1057.31 2779.23,1057.31 2786.26,1064.34 R36.2@2786.26,1082.65 ; R36.2 2789.58,1085.97 2805.65,1085.97 v2(2806.91,1087.22) ; v2(2802,1159.84) 2802.98,1158.86 2823.44,1158.86 C8.2
  Bottom Layer w12: v2(2779.3,1354) 2779.3,1300.46 2802,1277.75 v2(2802,1159.84) 2802,1124.84 2806.91,1119.93 v2(2806.91,1087.22)
VSOLAR: C1.2 C2.2 C3.2 C4.2 P1.2 R1.2 R14.1 U2.5 U3.1 U3.3 U4.1 | length 1454.4
  Top Layer w12: C2.2 2517,937 2507,947 2507,961 ; 2534,1104 2554,1084 2554,1072 2558,1068 U3.1 ; 2534,1104.03 2514,1124.03 2514,1184 2580,1250 2649,1250 2667,1268 2672,1268 2672,1270 2676,1274 2718.97,1274 2726,1266.97 U2.5 ; 2542.01,1096.01 2552,1106 R1.2 ; U3.1@2552,1067 2513.03,1067 2505,1058.97 2505,1006.03 2507,1004.03 ; U3.3 2566,997 2514.03,997 2507,1004.03 ; P1.2 2818.83,817.17 2815,821 2818.92,824.92 2818.92,904.92 C4.2 2812,912 2812,914 2803,923 2772.52,923 2739.49,956.03 2720.97,956.03 2719,958 2715.2,954.2 2569.77,954.2 2569.47,954.5 2538.53,954.5 2538.23,954.2 2513.8,954.2 2507,961 ; R14.1@2915.23,946.23 2930.62,961.62 v2(2930.62,964.63) 2930.82,964.63 2943.19,977 U4.1 ; 2507,961 2507,1004.03
  Bottom Layer w12: P1.2 2827.84,824.48 2827.84,852.68 2843.47,868.31 2843.47,883.47 2922.33,962.33 2928.32,962.33 v2(2930.62,964.63)
pads on no net: U3.4 U4.4 U5.6 U5.7 XFID1.0 XFID1.1 XFID2.0 XFID2.1 XFID3.0 XFID3.1

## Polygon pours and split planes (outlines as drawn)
GND on Bottom Layer "NONET_L-01_P-001" (solid, remove dead copper, pour order 1): 2177,1738.3 2177,754 3170.32,754 3170.32,1737.3 3169.32,1738.3
GND on Top Layer "NONET_L-01_P-001" (solid, remove dead copper, pour order 2): 2176.39,1737.49 2176.39,753.18 3169.71,753.18 3169.71,1736.49 3168.71,1737.49

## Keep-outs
Top Layer:
  region: 3030,1688.4 2968,1688.4 2968,1638 3030,1638
Keep-Out Layer:
  lines w2: 2179,1658 2179,757 3163,757 3163,1737 2258,1737
  lines w5: 2181.45,1657.16 ccw(c2181.45,1735.9) 2260.19,1735.9
  text ".Layer_Name" at 3325,1314.25 h60

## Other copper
Top Layer:
  text ".Layer_Name" at 3321,1749 h60
Bottom Layer:
  text ".Layer_Name" at 3335,1495 h60

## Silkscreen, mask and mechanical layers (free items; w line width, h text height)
Top Overlay:
  text ".DOC_REV" at 3148,1439 h20 r90
  text ".DOC_NUM" at 3115,1433 h20 r90
  text ".Layer_Name" at 3325,1039 h60
  text "NEG" at 2603,838 h20
  text "+" at 2885,811.67 h20
  text "-" at 2639,808 h20
  text "POS" at 2882,783 h20
Bottom Overlay:
  rectangle: 2910.63,765.4 3153,863.82
  rectangle: 2183.75,764 2624,862.43
  rectangle: 2268.86,1631.44 3155.86,1729.86
  text "NEG" at 2750,883 h20
  text "POS" at 2846,880 h20
  text "-" at 2652,813 h20
  text "+" at 2874,811.67 h20
  text ".Layer_Name" at 3335,785 h60
Paste Mask Top:
  text ".Layer_Name" at 3325,1118 h60
Paste Mask Bottom:
  text ".Layer_Name" at 3331,695 h60
Top Solder:
  region: 2884,1676 2884,1671 2884,1625 2948,1625 2950,1627 2950,1676
  text ".Layer_Name" at 3331,947 h60
Bottom Solder:
  text ".Layer_Name" at 3336,861 h60
Drill Guide:
  text ".Layer_Name" at 3325,1401.88 h60
Mechanical 1:
  text ".Layer_Name" at 3321,1841 h60
Outline:
  lines w5.98: 2177.35,1659.96 ccw(c2177.35,1738.7) 2256.09,1738.7
  lines w6: 2177,1659.96 2177,754 3165,754 3165,1739 2256.09,1739
  text ".Layer_Name" at 3319,1661 h60
Fab Notes:
  lines w10: 5607,6503.02 9634.86,6503.02 ; 7267.54,4394 7267.54,6728.02 ; 8684.86,4394 8684.86,6728.02 ; 9627.86,6728.06 5607,6728.06 5607,4394 9635.86,4394 9635.86,6732.02 ; 6912.48,3760.52 9112.48,3760.52 9112.48,4010.52 6912.48,4010.52 6912.48,3760.52 ; 6912.48,3785.52 9112.48,3785.52 8912.48,3985.52 8712.48,3785.52 8512.48,3985.52 8312.48,3785.52 8112.48,3985.52 7912.48,3785.52 7712.48,3985.52 7512.48,3785.52 7312.48,3985.52 7112.48,3785.52 6912.48,3985.52 9112.48,3985.52 8912.48,3785.52 8712.48,3985.52 8512.48,3785.52 8312.48,3985.52 8112.48,3785.52 7912.48,3985.52 7712.48,3785.52 7512.48,3985.52 7312.48,3785.52 7112.48,3985.52 6912.48,3785.52
  text "Layer/function" at 6384.86,6578.02 h60
  text "Pcb File Name \"Root\"" at 7394.53,6578.02 h60
  text "file extension" at 8759.86,6578.02 h60
  text ".OutputName" at 7309.86,6379.02 h60
  text "Top Solder :" at 6515.18,6378.02 h60
  text "Top Solder :" at 6515.18,6378.02 h60
  text ".GTS" at 8962.42,6378.02 h60
  text ".OutputName" at 7309.86,6279.02 h60
  text "Top Paste :" at 6575.16,6278.02 h60
  text ".GTP" at 8962.42,6278.02 h60
  text ".OutputName" at 7309.86,6179.02 h60
  text "Top Overlay :" at 6455.2,6178.02 h60
  text ".GTO" at 8962.42,6178.02 h60
  text ".OutputName" at 7309.86,6079.02 h60
  text "Top Layer :" at 6565.16,6078.02 h60
  text ".GTL" at 8962.42,6078.02 h60
  text "Mid Layer 1 :" at 6465.2,5979.02 h60
  text ".Print_Date" at 1806.5,5961.15 h40
  text ".Print_Time" at 2577.3,5954.95 h40
  text "FABRICATION NOTES" at 1802,5869 h60
  text "GND_Plane :" at 6575.16,5865 h60
  text "1. PCB CONSTRUCTION: 2 LAYERS, AS SHOWN IN STACK-UP DETAIL." at 2077.04,5787.96 h60
  text "Power/Route :" at 6455.2,5770 h60
  text "2. MATERIAL" at 2076.98,5692.35 h60
  text "Mid Layer 3 :" at 6455.2,5668.02 h60
  text "A. LAMINATE: 0.062\" +/- 10% LAMINATE MATERIAL TO BE POLYCLAD 370HR OR NELCO N4000-29" at 2260.16,5605.76 h60
  text "Power Plane :" at 6455.2,5586 h60
  text "OR EQUIVALENT AND CAPABLE OF WITHSTANDING A NO LEAD SOLDER PROCESS" at 2423,5519.28 h60
  text "Mid Layer 4 :" at 6455.2,5502 h60
  text "Bottom Layer :" at 6405.22,5405.97 h60
  text ".GBL" at 8962.42,5386.28 h60
  text ".OutputName" at 7309.86,5382.28 h60
  text "C. 0.5 OZ COPPER ON EXTERNAL LAYERS, PLATED TO 1.5 OZ MIN. (2 OZ PREFERRED) FINISHED WEIGHT." at 2260.16,5351.64 h60
  text "Bottom Solder :" at 6355.23,5302 h60
  text ".GBS" at 8962.42,5287.86 h60
  text ".OutputName" at 7309.86,5283.86 h60
  text "D. TOLERANCE: PER IPC-D-275" at 2260.16,5253 h60
  text "Bottom Paste :" at 6415.21,5221.97 h60
  text ".GBP" at 8962.42,5202.28 h60
  text ".OutputName" at 7309.86,5198.28 h60
  text "Bottom Overlay :" at 6295.25,5123.54 h60
  text ".GBO" at 8962.42,5103.86 h60
  text ".OutputName" at 7309.86,5099.86 h60
  text "F.HASL FINISH" at 2260.16,5087.64 h60
  text "Board Outline :" at 6355.23,5023 h60
  text ".GM3" at 8962.42,5011 h60
  text ".OutputName" at 7309.86,5004.86 h60
  text "3. PROCESSING TOLERANCES:" at 2077.04,4989 h60
  text "Board Dimensions :" at 6165.29,4927 h60
  text ".OutputName" at 7309.86,4919.28 h60
  text "A. CONDUCTIVE PATTERN FRONT TO BACK, REGISTRATION +/- 0.005\"" at 2260.16,4907.96 h60
  text ".GM12" at 8962.42,4908 h60
  text "Fab Notes :" at 6575.16,4834 h60
  text ".OutputName" at 7309.86,4820.86 h60
  text ".GM4" at 8962.42,4816 h60
  text "B. MINIMUM AVERAGE PLATED THROUGH HOLE THICKNESS 0.001\" WITH NO READING LESS THAN 0.0004\"" at 2260.16,4813 h60
  text "Drill Drawing :" at 6365.23,4739 h60
  text ".OutputName" at 7309.86,4729.28 h60
  text "C. FINISHED HOLE TOLERANCES AS FOLLOWS UNLESS OTHERWISE INDICATED:" at 2260.16,4725 h60
  text ".GD1" at 8962.42,4718 h60
  text "NC Drill File (ASCII) :" at 5932,4645 h60
  text ".OutputName" at 7301.86,4640.28 h60
  text "PLATED +/- 0.003" at 2422.89,4637 h60
  text ".TXT" at 8954.42,4629 h60
  text "NON-PLATED: +/- 0.003" at 2423,4549 h60
  text "NC Drill File (BIN) :" at 6037,4539 h60
  text ".OutputName" at 7306.86,4533.28 h60
  text ".DRL" at 8959.42,4522 h60
  text "D. MINIMUM ANNULAR RING FOR VIAS 0.006\"" at 2260.16,4461 h60
  text "E. MINIMUM CONDUCTOR WIDTH 0.012\"" at 2260.16,4373 h60
  text "F. MINIMUM INTER-CONDUCTOR SPACE 0.010\"" at 2260.16,4285 h60
  text "4. DIMENSIONS:" at 2077.04,4197 h60
  text "Top Overlay" at 7712.48,4135.52 h60
  text "A. INSIDE CORNER RADII <= 1.0MM" at 2260.16,4109 h60
  text "5. WARP AND TWIST:" at 2077.04,4021 h60
  text "Top Layer -->" at 6117.74,3985.52 h60
  text "A. WITHIN 0.010\" PER INCH MAX" at 2260.16,3933 h60
  text "6. SOLDER MASK" at 2077.04,3845 h60
  text "<-- Core" at 9157.48,3835.06 h60
  text "A. LPI SMOBC 2 SIDE, PER IPC-SM-840, REV C, CLASS H" at 2260.16,3763.96 h60
  text "Bottom Layer -->" at 5951,3744 h60
  text "B. COLOR = GREEN" at 2260.16,3669 h60
  text "Bottom Overlay" at 7625,3631 h60
  text "C. NO MASK ALLOWED ON TERMINAL AREAS, COMPONENT SOLDER PADS & TEST POINTS" at 2260.16,3587.96 h60
  text "D. SOLDER MASK TO ETCH REGISTRATION WITHIN 0.003\" TOTAL" at 2260.16,3493 h60
  text "Board Stackup" at 7478,3421 h100
  text "E. MASK OPENINGS THAT ARE 1:1 WITH THE COPPER PADS SHOULD BE ADJUSTED BY THE FABRICATOR AS NEEDED" at 2260.16,3405 h60
  text "7. SILKSCREEN:" at 2077.04,3317 h60
  text "A. NON-CONDUCTIVE WHITE EPOXY INK ON BOTH SIDES" at 2260.16,3229 h60
  text "B. NOMENCLATURE SHALL BE COMPLETE AND LEGIBLE PER IPC-D-275 AND IPC-A-600" at 2260.16,3141 h60
  text "C. MERGE SOLDERMASK AND SILKSCREEN - NO SILKSCREEN ALLOWED ON EXPOSED COPPER" at 2260.16,3053 h60
  text "10. BOARDS TO BE 100% TESTED TO IPC-D-3506A NETLIST - NO REWORK" at 2077.04,2613.76 h60
  text "11. AUTO THEIVING IS NOT ACCEPTABLE EXCEPT ON PALLET OUTSIDE BOARD AREA" at 2077.04,2525 h60
  text "For any questions please contact Mikhail Fridberg - 781-327-2037 - fridberg@adspconsulting.com" at 2081,1887 h60
  text ".Layer_Name" at 3325,1585 h60
Drill Drawing:
  text ".Layer_Name" at 3325,1206.62 h60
